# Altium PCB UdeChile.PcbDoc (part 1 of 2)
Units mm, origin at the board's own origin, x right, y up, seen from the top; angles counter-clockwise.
Board outline 201.93 x 30.26 mm, 2 copper layers (Top Layer, Bottom Layer); 212 components, 140 nets, 743 pads, 138 vias.
Unrouted connection lines stored in the file: 2.
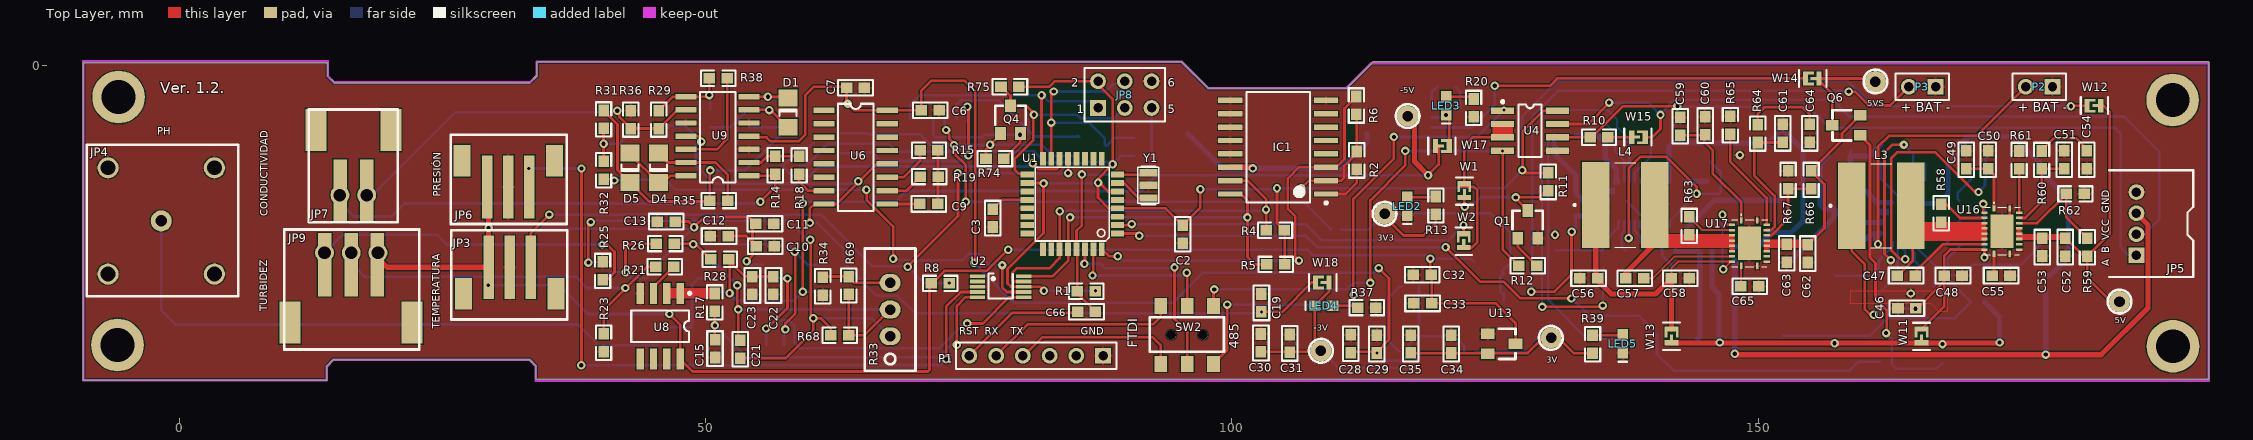
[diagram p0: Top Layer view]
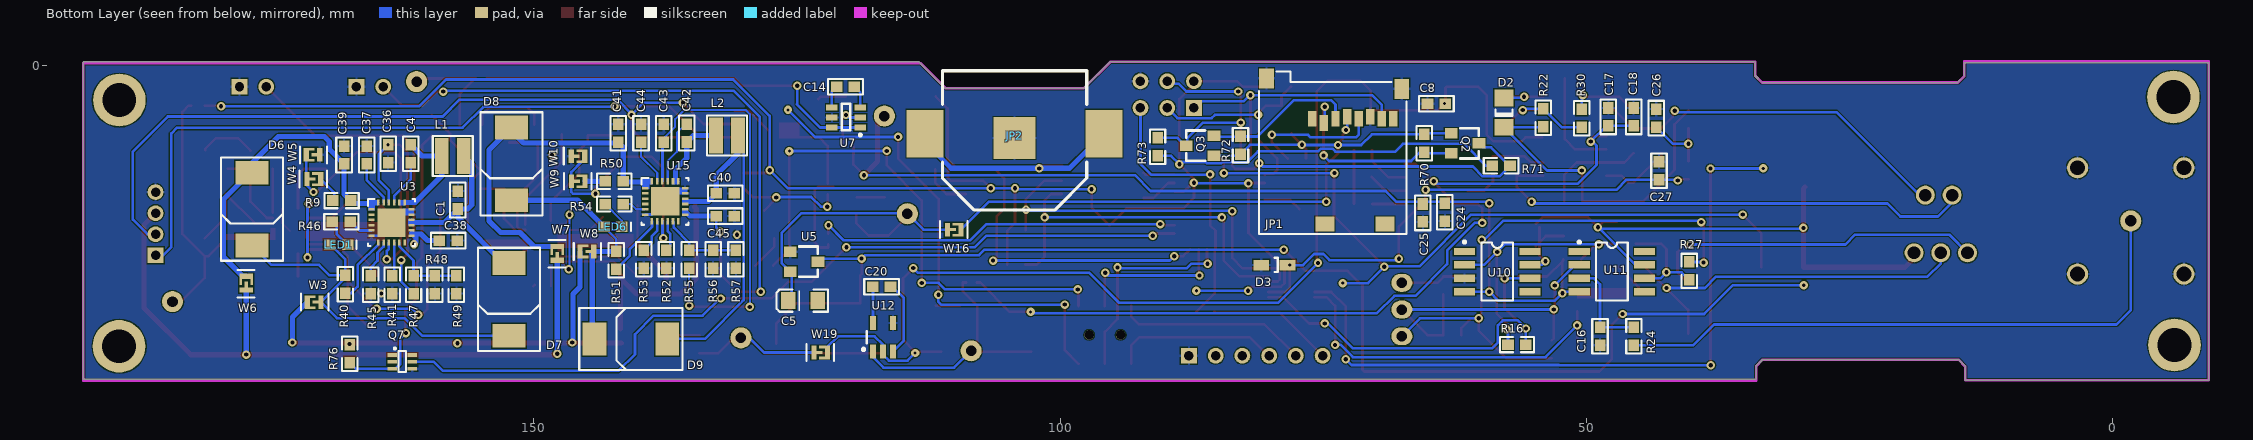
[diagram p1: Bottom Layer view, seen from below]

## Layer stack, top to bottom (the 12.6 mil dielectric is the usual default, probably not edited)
Top Layer: signal copper 0.0356
Dielectric: dielectric 0.32, FR-4, Dk 4.8
Bottom Layer: signal copper 0.0356

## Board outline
-9.13,-29.914 14.011,-29.914 14.011,-28.592 14.651,-27.952 33.247,-27.952 33.875,-28.58 33.875,-29.829 192.799,-29.829 192.799,0.339 192.796,0.336 113.375,0.336 110.88,-2.159 97.734,-2.159 95.23,0.345 95.224,0.339 33.949,0.339 33.949,-0.983 33.31,-1.622 14.713,-1.622 14.086,-0.995 14.086,0.264 -9.12,0.264 -9.13,0.254

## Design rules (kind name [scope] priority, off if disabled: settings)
Clearance [All] p1: gap=0.1
PolygonConnect [All] p1: connectstyle=Relief reliefconductorwidth=0.254 reliefentries=4 polygonreliefangle="90 Angle"
RoutingVias [All] p1: holewidth=0.711 width=1.27 viastyle="Through Hole" minholewidth=0.711 minwidth=1.27 maxholewidth=0.711 maxwidth=1.27
SilkscreenOverComponentPads SilkToSolderMaskClearance [IsPad] p1: minsilkscreentomaskgap=0.254
SolderMaskExpansion [All] p1: expansion=0.102
Width [All] p1: maxlimit=0.5 minlimit=0.2 preferedwidth=0.25
27 further rules are at their usual default settings.

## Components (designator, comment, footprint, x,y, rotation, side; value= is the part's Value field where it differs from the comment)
C1 "0.1uF" "Cap 0.1uF 0603 SMD" 157.202,-12.786 r270 bottom
C2 "0.1uF" "Cap 0.1uF 0603 SMD" 95.312,-16.034 r90 top
C3 "0.1uF" "Cap 0.1uF 0603 SMD" 77.261,-14.501 r90 top
C4 "47nF" "Cap 0.1uF 0603 SMD" 161.671,-8.382 r90 bottom
C5 "100uF" "Cap tant 10uF 1206 SMD" 123.011,-22.344 r0 bottom
C6 "0.1uF" "Cap 0.1uF 0603 SMD" 71.332,-4.262 r0 top
C7 "4.7uF" "Cap 0.1uF 0603 SMD" 64.236,-2.131 r180 top
C8 "0.1uF" "Cap 0.1uF 0603 SMD" 64.242,-3.64 r180 bottom
C9 "1nF" "Cap 0.1uF 0603 SMD" 71.2,-13.159 r0 top
C10 "0.1uF" "Cap 0.1uF 0603 SMD" 55.665,-17.172 r180 top
C11 "10uF" "Cap 0.1uF 0603 SMD" 55.628,-15.047 r180 top
C12 "0.1uF" "Cap 0.1uF 0603 SMD" 51.28,-16.206 r0 top
C13 "10uF" "Cap 0.1uF 0603 SMD" 46.249,-14.831 r0 top
C14 "0.1uF" "Cap 0.1uF 0603 SMD" 120.383,-2.013 r180 bottom
C15 "0.1uF" "Cap 0.1uF 0603 SMD" 50.892,-26.9 r270 top
C16 "2.2nF" "Cap 0.1uF 0603 SMD" 48.701,-25.735 r270 bottom
C17 "4.7uF" "Cap 0.1uF 0603 SMD" 47.906,-4.891 r90 bottom
C18 "0.1uF" "Cap 0.1uF 0603 SMD" 45.515,-4.891 r90 bottom
C19 "0.1uF" "Cap 0.1uF 0603 SMD" 102.802,-22.565 r90 top
C20 "0.1uF" "Cap 0.1uF 0603 SMD" 116.954,-21.04 r0 bottom
C21 "1uF" "Cap 0.1uF 0603 SMD" 53.295,-26.97 r90 top
C22 "0.1uF" "Cap 0.1uF 0603 SMD" 56.442,-20.907 r270 top
C23 "10uF" "Cap 0.1uF 0603 SMD" 54.446,-20.907 r270 top
C24 "0.1uF" "Cap 0.1uF 0603 SMD" 63.442,-13.943 r270 bottom
C25 "10uF" "Cap 0.1uF 0603 SMD" 65.529,-14.013 r270 bottom
C26 "1uF" "Cap 0.1uF 0603 SMD" 43.366,-5.004 r90 bottom
C27 "1uF" "Cap 0.1uF 0603 SMD" 43.098,-9.996 r90 bottom
C28 "0.1uF" "Cap 0.1uF 0603 SMD" 111.283,-26.443 r270 top
C29 "0.1uF" "Cap 0.1uF 0603 SMD" 113.765,-26.466 r270 top
C30 "0.1uF" "Cap 0.1uF 0603 SMD" 102.755,-26.367 r270 top
C31 "0.1uF" "Cap 0.1uF 0603 SMD" 105.49,-26.411 r270 top
C32 "0.1uF" "Cap 0.1uF 0603 SMD" 118.073,-19.885 r0 top
C33 "0.1uF" "Cap 0.1uF 0603 SMD" 118.114,-22.609 r0 top
C34 "0.1uF" "Cap 0.1uF 0603 SMD" 120.838,-26.466 r270 top
C35 "0.1uF" "Cap 0.1uF 0603 SMD" 116.973,-26.465 r270 top
C36 "4.7uF" "Cap 0.1uF 0603 SMD" 163.83,-8.382 r270 bottom
C37 "10uF" "Cap 0.1uF 0603 SMD" 165.862,-8.509 r270 bottom
C38 "10uF" "Cap 0.1uF 0603 SMD" 158.115,-16.637 r0 bottom
C39 "10uF" "Cap 0.1uF 0603 SMD" 168.021,-8.509 r270 bottom
C40 "0.1uF" "Cap 0.1uF 0603 SMD" 131.805,-12.152 r0 bottom
C41 "10uF" "Cap 0.1uF 0603 SMD" 141.965,-6.437 r270 bottom
C42 "47nF" "Cap 0.1uF 0603 SMD" 135.453,-6.42 r270 bottom
C43 "4.7uF" "Cap 0.1uF 0603 SMD" 137.647,-6.437 r90 bottom
C44 "10uF" "Cap 0.1uF 0603 SMD" 139.806,-6.437 r270 bottom
C45 "10uF" "Cap 0.1uF 0603 SMD" 131.805,-14.311 r0 bottom
C46 "0.1uF" "Cap 0.1uF 0603 SMD" 164.122,-23.063 r180 top
C47 "0.1uF" "Cap 0.1uF 0603 SMD" 164.047,-19.96 r0 top
C48 "47uF" "Cap 0.1uF 0603 SMD" 168.503,-19.963 r180 top
C49 "1uF" "Cap 0.1uF 0603 SMD" 169.747,-8.96 r90 top
C50 "1uF" "Cap 0.1uF 0603 SMD" 171.841,-8.96 r90 top
C51 "51pF" "Cap 0.1uF 0603 SMD" 179.064,-8.96 r90 top
C52 "47uF" "Cap 0.1uF 0603 SMD" 179.178,-17.262 r270 top
C53 "47uF" "Cap 0.1uF 0603 SMD" 176.98,-17.255 r270 top
C54 "1nF" "Cap 0.1uF 0603 SMD" 181.219,-8.958 r270 top
C55 "82nF" "Cap 0.1uF 0603 SMD" 173.066,-19.96 r0 top
C56 "0.1uF" "Cap 0.1uF 0603 SMD" 133.884,-20.221 r180 top
C57 "0.1uF" "Cap 0.1uF 0603 SMD" 138.259,-20.218 r0 top
C58 "47uF" "Cap 0.1uF 0603 SMD" 142.599,-20.221 r180 top
C59 "1uF" "Cap 0.1uF 0603 SMD" 142.586,-5.788 r90 top
C60 "1uF" "Cap 0.1uF 0603 SMD" 144.948,-5.719 r90 top
C61 "51pF" "Cap 0.1uF 0603 SMD" 152.334,-6.457 r90 top
C62 "47uF" "Cap 0.1uF 0603 SMD" 154.718,-17.875 r270 top
C63 "47uF" "Cap 0.1uF 0603 SMD" 152.698,-17.85 r270 top
C64 "1nF" "Cap 0.1uF 0603 SMD" 154.903,-6.456 r270 top
C65 "82nF" "Cap 0.1uF 0603 SMD" 149.198,-20.988 r0 top
C66 "0.1uF" "Cap 0.1uF 0603 SMD" 86.181,-23.388 r180 top
D1 "1N4148" "Diodo 1N4148 SMD" 57.824,-5.879 r90 top
D2 "1N4148" "Diodo 1N4148 SMD" 57.824,-3.079 r270 bottom
D3 "SDM100K30L-7" "Diodo SDM100K30L-7 SMD" 80.886,-18.974 r180 bottom
D4 "1N4148" "Diodo 1N4148 SMD" 45.512,-8.331 r270 top
D5 "1N4148" "Diodo 1N4148 SMD" 42.824,-8.331 r270 top
D6 "SM15T36CA" SM15T36CA 177.165,-12.827 r270 bottom
D7 "SM15T36CA" SM15T36CA 152.751,-21.395 r270 bottom
D8 "SM15T36CA" SM15T36CA 152.507,-8.522 r270 bottom
D9 "SM15T36CA" SM15T36CA 139.957,-25.588 r0 bottom
IC1 "DS3231" "RTC DS323116-SOIC" 108.946,-12.21 r180 top
JP1 "Socket uSD" "uSD Socket" 81.089,-15.896 r270 bottom
JP2 "Socket SMD" "Socket Pila 12mm SMD" 104.323,-6.885 r180 bottom
JP3 "3 pines" "JST SMD 3 PINES" 31.381,-19.177 r0 top
JP4 "BNC Conector" "BNC Conector" -1.718,-14.772 r90 top
JP5 "Grove" "JST TH 4 Pines - Horizontal" 185.928,-18.034 r0 top
JP6 "3 pines" "JST SMD 3 PINES" 31.254,-11.557 r180 top
JP7 "JST SMD" "JST SMD 2 pines - 2.54mm" 17.795,-11.938 r180 top
JP8 "ISP" HDR2X3 87.28,-4.039 r0 top
JP9 "3 pines" "JST SMD 3 PINES - 2.54mm" 16.317,-18.94 r0 top
L1 "1uH" 74438336010 157.607,-8.636 r180 bottom
L2 "1uH" 74438336010 131.551,-6.691 r180 bottom
L3 "1uH" SRN8040-1R0Y 162.28,-13.569 r0 top
L4 "1uH" SRN8040-1R0Y 137.957,-13.494 r0 top
LED1 "LED Rojo" "LED Rojo 0603" 168.529,-17.018 r180 bottom
LED2 "LED Rojo" "LED Rojo 0603" 116.674,-13.364 r270 top
LED3 "LED Rojo" "LED Rojo 0603" 120.365,-3.815 r270 top
LED4 "LED Rojo" "LED Rojo 0603" 108.702,-22.838 r180 top
LED5 "LED Rojo" "LED Rojo 0603" 137.142,-26.448 r270 top
LED6 "LED Rojo" "LED Rojo 0603" 142.473,-15.327 r180 bottom
P1 "Header 6" HDR1X6 87.758,-27.577 r180 top
P2 "Header 2" HDR1X2 177.953,-2.022 r180 top
P3 "Header 2" HDR1X2 166.849,-2.022 r180 top
Q1 "BSS123" "MOSFET BSS123  SMD SOT-23" 128.1,-15.105 r0 top
Q2 "BSS123" "MOSFET BSS123  SMD SOT-23" 61.524,-7.399 r270 bottom
Q3 "BSS123" "MOSFET BSS123  SMD SOT-23" 86.694,-7.613 r90 bottom
Q4 "BSS123" "MOSFET BSS123  SMD SOT-23" 78.962,-5.147 r0 top
Q6 "FDN340P" "MOSFET FDN340P SSOT3" 158.356,-5.75 r90 top
Q7 "DDC123JU" "Transistor array DDC123JU-FDICT SMD" 163.445,-27.509 r270 bottom
R1 "10K" "Res 1K 0603 1/8W" 86.156,-21.448 r0 top
R2 "10K" "Res 10K 0603 1/10W" 111.853,-9.027 r270 top
R4 "22K" "Res 1K 0603 1/8W" 104.102,-15.652 r0 top
R5 "22K" "Res 1K 0603 1/8W" 104.153,-18.906 r0 top
R6 "10K" "Res 10K 0603 1/10W" 111.825,-3.804 r90 top
R8 "4k7" "Res 10K 0603 1/10W" 72.284,-20.71 r0 top
R9 "10K" "Res 1K 0603 1/8W" 168.252,-12.831 r0 bottom
R10 "120R" "Res 1K 0603 1/8W" 134.871,-6.812 r180 top
R11 "10K" "Res 10K 0603 1/10W" 130.054,-11.064 r90 top
R12 "Res 10K SMD" "Res 10K 0603 1/10W" 128.1,-19.022 r180 top
R13 "1K" "Res 1K 0603 1/8W" 119.378,-13.305 r270 top
R14 "6K8" "Res 1K 0603 1/8W" 56.608,-9.478 r90 top
R15 "100K" "Res 1K 0603 1/8W" 71.219,-8.058 r0 top
R16 "30K" "Res 1K 0603 1/8W" 56.591,-26.524 r180 bottom
R17 "1K" "Res 1K 0603 1/8W" 50.877,-22.513 r90 top
R18 "100K" "Res 1K 0603 1/8W" 58.873,-9.492 r270 top
R19 "10K" "Res 1K 0603 1/8W" 71.238,-10.562 r0 top
R20 "1K" "Res 1K 0603 1/8W" 122.962,-4.04 r90 top
R21 "10K" "Res 1K 0603 1/8W" 46.109,-19.131 r180 top
R22 "10k" "Res 1K 0603 1/8W" 54.09,-4.972 r90 bottom
R23 "4K7" "Res 1K 0603 1/8W" 40.301,-26.338 r90 top
R24 "4M7" "Res 1K 0603 1/8W" 45.483,-25.735 r270 bottom
R25 "500R" "Res 1K 0603 1/8W" 40.205,-19.515 r270 top
R26 "30K" "Res 1K 0603 1/8W" 46.152,-16.926 r0 top
R27 "2K2" "Res 1K 0603 1/8W" 40.228,-19.52 r90 bottom
R28 "75K" "Res 1K 0603 1/8W" 51.333,-18.409 r180 top
R29 "5K6" "Res 1K 0603 1/8W" 45.547,-5.146 r270 top
R30 "10k" "Res 1K 0603 1/8W" 50.432,-5.021 r90 bottom
R31 "10k" "Res 1K 0603 1/8W" 40.301,-5.13 r90 top
R32 "10k" "Res 1K 0603 1/8W" 40.301,-9.961 r90 top
R33 "TRIM 5K" "TRIMPOT TH" 67.528,-23.193 r180 top
R34 "1K" "Res 1K 0603 1/8W" 61.135,-20.985 r90 top
R35 "10k" "Res 1K 0603 1/8W" 51.245,-12.841 r0 top
R36 "1M" "Res 1K 0603 1/8W" 42.891,-5.146 r90 top
R37 "1K" "Res 1K 0603 1/8W" 112.804,-22.999 r180 top
R38 "10k" "Res 1K 0603 1/8W" 51.202,-1.22 r180 top
R39 "1K" "Res 1K 0603 1/8W" 134.252,-26.49 r270 top
R40 "2k2" "Res 1K 0603 1/8W" 167.894,-20.789 r270 bottom
R41 "1K" "Res 1K 0603 1/8W" 163.449,-20.828 r270 bottom
R45 "1K" "Res 1K 0603 1/8W" 165.481,-20.828 r270 bottom
R46 "2K2" "Res 1K 0603 1/8W" 168.275,-14.859 r180 bottom
R47 "5K23" "Res 1K 0603 1/8W" 161.417,-20.828 r270 bottom
R48 "30K" "Res 1K 0603 1/8W" 159.385,-20.828 r90 bottom
R49 "10K" "Res 1K 0603 1/8W" 157.353,-20.828 r90 bottom
R50 "10K" "Res 1K 0603 1/8W" 142.346,-11.009 r0 bottom
R51 "2k2" "Res 1K 0603 1/8W" 142.159,-18.503 r270 bottom
R52 "1K" "Res 1K 0603 1/8W" 137.393,-18.417 r270 bottom
R53 "1K" "Res 1K 0603 1/8W" 139.552,-18.417 r270 bottom
R54 "2K2" "Res 1K 0603 1/8W" 142.346,-13.168 r180 bottom
R55 "5K23" "Res 1K 0603 1/8W" 135.234,-18.417 r270 bottom
R56 "30K" "Res 1K 0603 1/8W" 132.955,-18.419 r90 bottom
R57 "10K" "Res 1K 0603 1/8W" 130.789,-18.419 r90 bottom
R58 "332K" "Res 1K 0603 1/8W" 167.376,-14.05 r270 top
R59 "324K" "Res 1K 0603 1/8W" 181.272,-17.272 r270 top
R60 "17K4" "Res 1K 0603 1/8W" 176.911,-8.976 r270 top
R61 "270K" "Res 1K 0603 1/8W" 174.772,-8.976 r270 top
R62 "100k" "Res 1K 0603 1/8W" 180.126,-12.208 r180 top
R63 "332K" "Res 1K 0603 1/8W" 143.442,-15.245 r270 top
R64 "17K4" "Res 1K 0603 1/8W" 149.941,-6.473 r270 top
R65 "270K" "Res 1K 0603 1/8W" 147.356,-5.672 r270 top
R66 "324K" "Res 1K 0603 1/8W" 155.022,-10.873 r90 top
R67 "100k" "Res 1K 0603 1/8W" 152.83,-10.873 r270 top
R68 "0" "Res 1K 0603 1/8W" 62.732,-25.629 r0 top
R69 "0" "Res 1K 0603 1/8W" 63.591,-20.907 r90 top
R70 "10K" "Res 10K 0603 1/10W" 65.402,-7.389 r90 bottom
R71 "10K" "Res 10K 0603 1/10W" 58.104,-9.534 r0 bottom
R72 "10K" "Res 10K 0603 1/10W" 82.856,-7.597 r270 bottom
R73 "10K" "Res 10K 0603 1/10W" 90.733,-7.734 r270 bottom
R74 "10K" "Res 10K 0603 1/10W" 77.482,-8.847 r180 top
R75 "10K" "Res 10K 0603 1/10W" 78.909,-2.028 r0 top
R76 "1K" "Res 1K 0603 1/8W" 167.485,-27.398 r90 bottom
SW2 "DPDT SMD" "SW INTERR SMD" 94.243,-25.605 r90 top
U1 "ATMEGA328" "ATMega328 32-TQFP SMD" 89.126,-15.971 r180 top
U2 "ADS1015IDGSR" ADS1015IDGSR 78.026,-21.007 r0 top
U3 "BQ25606RGER" BQ25606RGER 163.322,-14.986 r180 bottom
U4 "SN75176AD" "Transceiver SN75176AD SOCI8" 125.712,-4.297 r0 top
U5 "AP2120N-3.3TRG1" "Reg 3.3V 150mA SOT-23" 124.31,-18.649 r270 bottom
U6 "CD4060BM96" "C BINARY COUNTER/DIV/OSC CD4060BM 16SOIC" 64.252,-8.728 r0 top
U7 "LTC1983ES6-5" "Reg CHARGE PUMP -5V SOT-23-6" 118.979,-5.893 r90 bottom
U8 "LM358" "Op Amp LM358 8-SOIC SMD" 45.686,-24.765 r270 top
U9 "LMV324" "Op. Amp LM324 SO-14" 54.118,-10.467 r180 top
U10 "TL081BCD" "Amp. Op. CA3140AMZ SOIC8" 58.467,-19.587 r180 bottom
U11 "CA3140AMZ" "Amp. Op. CA3140AMZ SOIC8" 47.565,-19.587 r180 bottom
U12 "TPS60400DBVR" "Charge Pump Switching Regulator - TPS60400DBVR" 117.776,-27.17 r90 bottom
U13 "AP7361-33D" "Reg 3V 300mA SOT23-3" 125.625,-26.448 r270 top
U15 "BQ25606RGER" BQ25606RGER 137.328,-12.974 r180 bottom
U16 "TPS61088RHLR" TPS61088RHLR 173.255,-15.668 r0 top
U17 "TPS61088RHLR" TPS61088RHLR 149.258,-16.818 r0 top
W1 "Jumper" Jumper 122.082,-11.936 r90 top
W2 "Jumper" Jumper 122.022,-16.699 r90 top
W3 "Jumper" Jumper 170.815,-22.489 r0 bottom
W4 "Jumper" Jumper 170.942,-10.795 r180 bottom
W5 "Jumper" Jumper 170.923,-8.492 r0 bottom
W6 "Jumper" Jumper 177.318,-20.738 r90 bottom
W7 "Jumper" Jumper 147.769,-17.901 r90 bottom
W8 "Jumper" Jumper 144.898,-17.669 r0 bottom
W9 "Jumper" Jumper 145.82,-11.005 r180 bottom
W10 "Jumper" Jumper 145.846,-8.625 r180 bottom
W11 "Jumper" Jumper 165.513,-25.744 r90 top
W12 "Jumper" Jumper 181.938,-3.82 r180 top
W13 "Jumper" Jumper 141.764,-25.739 r90 top
W14 "Jumper" Jumper 155.181,-1.244 r180 top
W15 "Jumper" Jumper 138.574,-6.812 r0 top
W16 "Jumper" Jumper 110.099,-15.603 r180 bottom
W17 "Jumper" Jumper 119.946,-7.658 r0 top
W18 "Jumper" Jumper 108.628,-20.619 r180 top
W19 "Jumper" Jumper 122.785,-27.275 r180 bottom
Y1 "16MHz" "Xtal 16MHz SMD" 92.067,-11.388 r270 top

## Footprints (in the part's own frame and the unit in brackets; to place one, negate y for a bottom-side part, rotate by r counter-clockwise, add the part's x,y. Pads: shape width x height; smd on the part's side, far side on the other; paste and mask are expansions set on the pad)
74438336010 [mm] "FIXED IND 1UH 4A 32 MOHM SMD"
  rect 1.3x3.4 smd: 1(-1.141,0.035) 2(0.959,0.035)
  silkscreen extent -1.99,-1.87 1.81,1.94, body extent -1.59,-1.46 1.41,1.54, height 2
ADS1015IDGSR [mm] "ADS1015IDGSR"
  rect 1.45x0.35 smd: 1(-2.2,0.975) 2(-2.2,0.475) 3(-2.2,-0.015) 4(-2.2,-0.515) 5(-2.2,-1.015) 6(2.2,-1.015) 7(2.2,-0.515) 8(2.2,-0.015) 9(2.2,0.475) 10(2.2,0.975)
  silkscreen extent -1.15,-1.15 1.15,1.25
"Amp. Op. CA3140AMZ SOIC8" [mm] "CA3140AMZ-ND"
  rect 2x0.7 smd: 1(-3.11,1.905) 2(-3.11,0.635) 3(-3.11,-0.635) 4(-3.11,-1.905) 5(3.11,-1.905) 6(3.11,-0.635) 7(3.11,0.635) 8(3.11,1.905)
  silkscreen extent -3.23,-2.75 1.5,2.93
"ATMega328 32-TQFP SMD" [mil] "ATMEGA328P-AU-ND, 556-ATMEGA328P-AU, ATMEGA328P-AU"
  rect 50x22 smd: 1(0,0) 2(0.01,-31.5) 3(0.01,-63) 4(0.01,-94.49) 5(0.01,-125.99) 6(0.01,-157.48) 7(0,-188.98) 8(0,-220.48) 17(338.01,-220.47) 18(338.01,-188.98) 19(338.01,-157.48) 20(338,-125.99) 21(338,-94.49) 22(338,-62.99) 23(338,-31.5) 24(338,-0.01)
  rect 22x50 smd: 9(58.77,-279.24) 10(90.26,-279.24) 11(121.76,-279.23) 12(153.26,-279.24) 13(184.75,-279.24) 14(216.25,-279.24) 15(247.74,-279.24) 16(279.24,-279.24) 25(279.24,58.76) 26(247.74,58.76) 27(216.25,58.76) 28(184.75,58.76) 29(153.26,58.76) 30(121.76,58.76) 31(90.27,58.76) 32(58.77,58.77)
  silkscreen extent 31,-248 307,28
"BNC Conector" [mm] "51K204-400A5"
  round 2 hole 1.1: 1(0,0)
  round 2 hole 1.4: 2(-5.05,-5.05) 2(-5.05,5.05) 2(5.05,-5.05) 2(5.05,5.05)
  silkscreen extent -7.15,-7.3 7.22,7.07, body extent -7.15,-7.3 7.22,26.92, height 14.5
BQ25606RGER [mm] "IC BATT CHG LI-ION 1CELL 24VQFN"
  rect 0.6x0.24 smd mask+0.07: 1(-2.092,1.31) 2(-2.092,0.81) 3(-2.092,0.31) 4(-2.092,-0.19) 5(-2.092,-0.69) 6(-2.092,-1.19) 13(1.708,-1.19) 14(1.708,-0.69) 15(1.708,-0.19) 16(1.708,0.31) 17(1.708,0.81) 18(1.708,1.31)
  rect 0.24x0.6 smd mask+0.07: 7(-1.442,-1.84) 8(-0.942,-1.84) 9(-0.442,-1.84) 10(0.058,-1.84) 11(0.558,-1.84) 12(1.058,-1.84) 19(1.058,1.96) 20(0.558,1.96) 21(0.058,1.96) 22(-0.442,1.96) 23(-0.942,1.96) 24(-1.442,1.96)
  rect 2.7x2.7 smd paste-1.337 mask+0.07: 25(-0.192,0.06)
  silkscreen extent -2.42,-2.16 2.03,2.29
"C BINARY COUNTER/DIV/OSC CD4060BM 16SOIC" [mm] "296-31513-2-ND"
  rect 2x0.51 smd: 1(-3,4.457) 2(-3,3.187) 3(-3,1.917) 4(-3,0.647) 5(-3,-0.623) 6(-3,-1.893) 7(-3,-3.163) 8(-3,-4.433) 9(3,-4.433) 10(3,-3.163) 11(3,-1.893) 12(3,-0.623) 13(3,0.647) 14(3,1.917) 15(3,3.187) 16(3,4.457)
  silkscreen extent -1.68,-5.09 1.7,5.09
"Cap 0.1uF 0603 SMD" [mm] "490-1532-2-ND, 81-GRM39X104K16, GRM188R71C104KA01D"
  rect 1.1x1 smd: 1(-0.85,0) 2(0.85,0)
  silkscreen extent -1.65,-0.74 1.65,0.74
"Cap tant 10uF 1206 SMD" [mm] "478-1655-1-ND, 581-TAJA106K016R, TAJA106K016RNJ"
  rect 1.4x1.6 smd: 1(2.8,0) 2(0,0)
  silkscreen extent -0.95,-1.06 3.91,1.05
"Charge Pump Switching Regulator - TPS60400DBVR" [mm] "2156-TPS60400DBVR-ND"
  rect 1.3x0.6 smd: 1(0,0) 2(0,-0.95) 3(0,-1.9) 4(2.7,-1.9) 5(2.7,0)
  silkscreen extent 0.08,0.6 1.92,1.01
"Diodo 1N4148 SMD" [mm] "568-1749-1-ND, 771-PMLL4148L-T/R, PMLL4148L 115"
  rect 1.6x1.8 smd: 1(0,0) 2(2.8,0)
  silkscreen extent 1.1,-0.8 1.7,0.8
"Diodo SDM100K30L-7 SMD" [mm] "SDM100K30LDITR-ND"
  rect 1.5x1 smd: 1(0,0) 2(2.5,0)
  silkscreen extent 1.25,-0.65 1.6,0.7
HDR1X2 [mm] "Connector; Header; 2 Position"
  rect 1.5x1.5 hole 0.9: 1(0,0)
  round 1.5 hole 0.9: 2(2.54,0)
  silkscreen extent -1.27,-1.27 3.81,1.27
HDR1X6 [mm] "Connector; Header; 6 Position"
  rect 1.5x1.5 hole 0.9: 1(0,0)
  round 1.5 hole 0.9: 2(2.54,0) 3(5.08,0) 4(7.62,0) 5(10.16,0) 6(12.7,0)
  silkscreen extent -1.27,-1.27 13.97,1.27
HDR2X3 [mm] "Connector; Header; 3x2 Position"
  rect 1.5x1.5 hole 0.9: 1(0,0)
  round 1.5 hole 0.9: 2(0,2.54) 3(2.54,0) 4(2.54,2.54) 5(5.08,0) 6(5.08,2.54)
  silkscreen extent -1.27,-1.27 6.35,3.81
"JST SMD 2 pines - 2.54mm" [mm]
  rect 1.3x6 smd: 1(2.5,0) 2(0,0)
  rect 2x4 smd: 3(4.8,-5.8) 4(-2.3,-5.8)
  silkscreen extent -2.95,-7.75 5.5,2.98, body extent -2.95,-7.75 5.45,3.03, height 7.9
"JST SMD 3 PINES" [mm] "455-1735-1-ND, , B3B-PH-SM4-TB(LF)(SN)(P)"
  rect 1x6 smd: 1(2,0) 2(0,0) 3(-2,0)
  rect 1.6x3 smd: 4(4.4,-2.5) 5(-4.4,-2.5)
  silkscreen extent -5.56,-4.96 5.46,3.51, body extent -5.43,-4.87 5.3,3.4, height 7.9
"JST SMD 3 PINES - 2.54mm" [mm] "455-1735-1-ND, , B3B-PH-SM4-TB(LF)(SN)(P)"
  rect 1.3x6 smd: 1(2.5,0) 2(0,0) 3(-2.5,0)
  rect 2x4 smd: 4(5.8,-5.5) 5(-5.8,-5.5)
  silkscreen extent -6.35,-8.05 6.48,3.35, body extent -6.35,-7.4 6.53,3.4, height 7.9
"JST TH 4 Pines - Horizontal" [mm] "Seeed: 110990030"
  rect 1.5x1.5 hole 0.9: 1(0,0)
  round 1.5 hole 0.9: 2(0,2) 3(0,4) 4(0,6)
  silkscreen extent -2.6,-2.08 5.41,8.08, body extent -2.7,-2.18 5.51,8.18, height 7.9
Jumper [mm]
  rect 0.5x1.3 smd: 1(-0.6,0) 2(0.7,0)
  rect 1x0.3 smd: 1(-0.3,0)
  rect 1x0.25 smd: 2(0.4,0.525) 2(0.4,-0.525)
  silkscreen extent -1.3,-0.8 1.3,0.8
"LED Rojo 0603" [mm] "475-2512-1-ND, 720-LSQ976-NR-1, LS Q976-NR-1"
  rect 1.1x1 smd: 1(-0.85,0) 2(0.85,0)
  silkscreen extent 1.7,-0.4 1.7,0.4
"MOSFET BSS123  SMD SOT-23" [mm] "BSS123NCT-ND, 512-BSS123, BSS123"
  rect 1x1.2 smd: 1(-0.95,-1.32) 2(0.95,-1.32) 3(0,1.32)
  silkscreen extent -1.44,-0.47 1.44,1.31
"MOSFET FDN340P SSOT3" [mm] "FDN340PCT-ND,,FDN340P"
  rect 1x1.2 smd: 1(-0.9,-1.32) 2(1,-1.32) 3(0.05,1.32)
  silkscreen extent -1.39,-0.47 1.49,1.31
"Op Amp LM358 8-SOIC SMD" [mm] "LM358DGOS-ND, 863-LM358DG, LM358DG"
  rect 2x0.7 smd: 1(-3.11,1.905) 2(-3.11,0.635) 3(-3.11,-0.635) 4(-3.11,-1.905) 5(3.11,-1.905) 6(3.11,-0.635) 7(3.11,0.635) 8(3.11,1.905)
  silkscreen extent -3.23,-2.75 1.5,2.93
"Op. Amp LM324 SO-14" [mm] "LMV324BG-13DITR-ND"
  rect 2x0.51 smd: 1(0,0) 2(0,-1.25) 3(0,-2.5) 4(0,-3.75) 5(0,-5) 6(0,-6.25) 7(0,-7.5) 8(6,-7.5) 9(6,-6.25) 10(6,-5) 11(6,-3.75) 12(6,-2.5) 13(6,-1.25) 14(6,0)
  silkscreen extent 1.27,-7.95 4.65,0.64
"Reg 3.3V 150mA SOT-23" [mm] "AP2120N-3.3TRG1DICT-ND,,AP2120N-3.3TRG1"
  rect 1x1.2 smd: 1(-0.95,-1.32) 2(0.95,-1.32) 3(0,1.32)
  silkscreen extent -1.44,-0.47 1.44,1.31
"Reg 3V 300mA SOT23-3" [mm] "AP2125N-3.0TRG1DITR-ND"
  rect 1x1.3 smd: 1(-0.95,-1.32) 2(0.95,-1.32) 3(0,1.32)
  silkscreen extent -1.44,-0.25 1.44,1.31
"Reg CHARGE PUMP -5V SOT-23-6" [mm] "LTC1983ES6-5#TRPBFTR-ND"
  rect 0.6x1.1 smd: 1(0,0) 2(0.95,0) 3(1.9,0) 4(1.9,2.7) 5(0.95,2.7) 6(0,2.7)
  silkscreen extent -0.82,-0.11 2.25,1.75
"Res 1K 0603 1/8W" [mm] "RNCP0603FTD1K00CT-ND, 660-SG73S1JTTD1001F, RNCP0603FTD1K00"
  rect 1.1x1 smd: 1(-0.85,0) 2(0.85,0)
  silkscreen extent -1.63,-0.73 1.63,0.73
"Res 10K 0603 1/10W" [mm] "P10KGCT-ND, 667-ERJ-3GEYJ103V, ERJ-3GEYJ103V"
  rect 1.1x1 smd: 1(-0.85,0) 2(0.85,0)
  silkscreen extent -1.65,-0.73 1.64,0.73
"RTC DS323116-SOIC" [mm] "DS3231SN#T&RTR-ND"
  rect 2.3x0.51 smd: 1(0,0) 2(0,-1.27) 3(0,-2.54) 4(0,-3.81) 5(0,-5.08) 6(0,-6.35) 7(0,-7.62) 8(0,-8.89) 9(9.1,-8.89) 10(9.1,-7.62) 11(9.1,-6.35) 12(9.1,-5.08) 13(9.1,-3.81) 14(9.1,-2.54) 15(9.1,-1.27) 16(9.1,0)
  silkscreen extent -0.13,-9.69 7.55,0.97
SM15T36CA [mm] "TVS DIODE 30.8V 64.3V SMC"
  rect 2.25x3.15 smd: 1(4.274,0.391) 2(-2.626,0.391)
  silkscreen extent -4.08,-2.56 5.72,3.34, body extent -3.15,-2.56 4.8,3.34, height 2.65
"Socket Pila 12mm SMD" [mm] "BK-885-ND, , BK-885"
  rect 3.5x4.5 smd: 1(-8.5,0.4) 1(8.5,0.4)
  rect 3.96x3.96 smd: 2(0,0)
  silkscreen extent -6.86,-6.86 6.86,6.38, body extent -6.85,-6.86 6.9,6.38, height 3.18
SRN8040-1R0Y [mm] "FIXED IND 1UH 7.8A 10 MOHM SMD"
  rect 2.6x8.2 smd: 1(-3.403,0.238) 2(2.197,0.238)
  silkscreen extent -5.5,-3.76 0.4,4.24, body extent -4.6,-3.76 3.4,4.24, height 4
"SW INTERR SMD" [mm] ", , ,spkf: COM-00597"
  rect 1.5x1.2 smd: 1(-2.75,1) 2(-2.75,-1.5) 3(-2.75,-4) 4(2.75,-4) 5(2.75,-1.5) 6(2.75,1)
  round 0.87 hole 0.9 mask+0.102: 7(0,0) 8(0,-3)
  silkscreen extent -1.61,-5 1.69,2.06
TPS61088RHLR [mm] "IC REG BOOST ADJ 10A 20VQFN"
  rect 0.24x0.6 smd mask+0.06: 1(-0.86,2.079) 10(-0.86,-2.221) 11(0.64,-2.221) 20(0.64,2.079)
  rect 0.6x0.24 smd mask+0.06: 2(-1.76,1.679) 3(-1.76,1.179) 4(-1.76,0.679) 6(-1.76,-0.321) 7(-1.76,-0.821) 8(-1.76,-1.321) 12(1.54,-1.821) 13(1.54,-1.321) 14(1.54,-0.821) 15(1.54,-0.321) 16(1.54,0.179) 17(1.54,0.679) 18(1.54,1.179) 19(1.54,1.679)
  rect 0.6x0.24 smd paste+0 mask+0.06: 5(-1.76,0.179) 9(-1.76,-1.821)
  rect 2.19x3.19 smd mask+0.06: 21(-0.11,-0.071)
  silkscreen extent -1.76,-2.32 1.64,2.68, body extent -1.86,-2.32 1.64,2.18, height 1.1
"Transceiver SN75176AD SOCI8" [mm] "296-6857-5-ND, 595-SN75176AD, SN75176AD"
  rect 2.2x0.6 smd: 1(0,0) 2(0,-1.27) 3(0,-2.54) 4(0,-3.81) 5(5.2,-3.81) 6(5.2,-2.54) 7(5.2,-1.27) 8(5.2,0)
  silkscreen extent -0.12,-4.4 3.7,0.97
"Transistor array DDC123JU-FDICT SMD" [mm] "DDC123JU-FDICT-ND, 621-DDC123JU-F, DDC123JU-7-F"
  rect 0.35x0.9 smd: 1(0,0) 2(0.65,0) 3(1.3,0) 4(1.3,1.9) 5(0.65,1.9) 6(0,1.9)
  silkscreen extent -0.69,0.18 1.61,1.3
"TRIMPOT TH" [mm] "3296W-103LF-ND, , 3296W-1-103LF"
  oval 2x1.7 hole 1: 1(0,2.54) 2(0,0) 3(0,-2.54)
  silkscreen extent -2.41,-5.8 2.41,5.8
"uSD Socket" [mm] "MCI-PRT-00176"
  rect 1.9x1.4 smd: 0(-14.675,0.7) 0(-13.675,13.55)
  rect 1.5x0.8 smd: 1(-10.825,5.06) 2(-10.425,6.16) 3(-10.825,7.26) 4(-11.025,8.36) 5(-10.825,9.46) 6(-11.025,10.56) 7(-10.825,11.66) 8(-10.825,12.76)
  rect 1.4x1.8 smd: 9(-0.825,6.25) 10(-0.825,11.95)
  silkscreen extent -15.32,0 0.13,14
"Xtal 16MHz SMD" [mm] "490-1198-1-ND, 81-CSTCE16M0V53-R0, CSTCE16M0V53-R0"
  rect 0.7x1.7 smd: 1(-1.2,0) 2(0,0) 3(1.2,0)
  silkscreen extent -1.8,-1 1.8,1

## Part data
C1 C2 C3 C4 C6 C8 C9 C10 C11 C12 C13 C15 C17 C19 C21 C22 C23 C24 C25 C28 C30 C32 C34 C36 C37 C38 C39 C40 C41 C42 C43 C44 C45 C46 C47 C48 C49 C50 C51 C52 C53 C54 C55 C56 C57 C58 C59 C60 C61 C62 C63 C64 C65 C66: library part "Capacitor 0.1uF SMD", "0.1uF 16V"
C5: library part "Cap TANT 100uF", "CAP TANT 100UF 6.3V 20% 1206"
C7 C18 C26 C27: library part "Capacitor 0.1uF SMD"
C14 C20: library part "Capacitor 0.1uF SMD", "1uF 16V"
C16: library part "Capacitor 0.1uF SMD", "2.2nF 16V"
C29 C31 C33 C35: library part "Capacitor 0.1uF SMD", "10uF 16V"
D1 D2 D4 D5: library part "Diodo 4148", "Diodo 4148 SMD"
D3: library part "Diodo SDM100K30L-7", "Diodo SDM100K30L-7 SMD"
D6 D7 D8 D9: "TVS DIODE 30.8V 64.3V SMC"
IC1: "IC RTC CLK/CALENDAR I2C 16-SOIC"
JP2: library part "Socket Pila 12mm SMD"
JP3 JP6: library part "JST 3 pines", "485-4391"
JP5: library part "JST 4 pines_Horizontal", "713-110990037"
JP7: library part "JST 2 pines_2.54mm", "2 pines"
JP8: library part "Header 3X2", "Header, 3-Pin, Dual row"
JP9: library part "JST 3 pines 2.54mm"
L1 L2: library part 74438336010, "FIXED IND 1UH 4A 32 MOHM SMD"
L3 L4: library part SRN8040-1R0Y, "FIXED IND 1UH 7.8A 10 MOHM SMD"
LED1 LED2 LED3 LED4 LED5 LED6: "LED Rojo 0603"
P1: "Header, 6-Pin"
P2 P3: "Header, 2-Pin"
Q1 Q2 Q3 Q4: library part "MOSFET N-Channel_2", "MOSFET N-CH 100V 170MA"
Q6: library part "MOSFET P-Channel_3", "MOSFET P-CH 20V 2A SSOT3"
Q7: library part "Trans Array Dual NPN", "Transistor Array 100mA"
R1 R4 R5 R9 R10 R13 R14 R15 R16 R17 R18 R19 R20 R21 R22 R23 R24 R25 R26 R27 R28 R29 R30 R31 R32 R34 R35 R36 R37 R38 R39 R40 R41 R45 R46 R47 R48 R49 R50 R51 R52 R53 R54 R55 R56 R57 R58 R59 R60 R61 R62 R63 R64 R65 R66 R67 R68 R69 R76: library part "Res 1K SMD", "1K SMD"
R2 R6 R11 R70 R71 R72 R73 R74 R75: library part "Res 10K SMD"
R8: library part "Res 10K SMD", "10K"
R12: "10K"
R33: library part "TRIMMER 10K OHM", "TRIMMER 10K OHM 0.5W PC PIN"
SW2: library part "SW interruptor"
U1: "IC ATMega328"
U3 U15: "IC BATT CHG LI-ION 1 CELL 24VQFN"
U4: "Transceiver Differential Bus 5V"
U5: library part "Reg 3.3V 150mA AP2120N", "IC REG LINEAR 3.3V 150MA SOT23"
U6: library part "IC Binary Counter Element Bit Negative"
U7: "REG CHARGE PUMP -5V TSOT23-6"
U8: library part "Op Amp 358", "Op Amp LM358"
U9: "Op. Amp. GP 4 CIRCUIT 14SO"
U10: "Operational Amplifier"
U11: "Operational Amplifier with MOSFET"
U12: library part "TPS60400 60MA CHARGE PUMP VOLTAG", "Reg. inv. -3v"
U13: library part "REG LINEAR 3V 300MA SOT23-3", "Regulador 3 0.3mA AP2125N-3.0TRG1"
U16 U17: "IC REG BOOST ADJ 10A 20VQFN"
W1 W2 W3 W4 W5 W6 W7 W8 W9 W10 W11 W12 W13 W14 W15 W16 W17 W18 W19: "Jumper Wire"
Y1: library part "XTAL 16MHz"

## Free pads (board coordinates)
  round 5 hole 3.2: 0(-5.872,-26.556) 0(-5.773,-3.004) 0(189.364,-3.29) 0(189.395,-26.679)
  round 1.8 hole 1.2: 1(18.87,-17.804) 2(16.33,-17.804) 2(17.795,-12.319) 3(13.79,-17.804) 3(15.255,-12.319)
  round 2 hole 1: 1(108.451,-27.11) 1(114.501,-14.09) 1(116.69,-4.809) 1(130.316,-25.882) 1(161.131,-1.538) 1(184.319,-22.44)

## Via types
v1: diameter 0.8/0.8 (per signal layer), hole 0.4, Top Layer to Bottom Layer, tented both sides, 126 vias
v2: diameter 0.8/0.8 (per signal layer), hole 0.3, Top Layer to Bottom Layer, tented bottom, 6 vias
v3: diameter 0.8/0.8 (per signal layer), hole 0.3, Top Layer to Bottom Layer, tented top, 3 vias
v4: diameter 0.6/0.8 (per signal layer), hole 0.3, Top Layer to Bottom Layer, tented bottom, 2 vias
v5: diameter 0.8/0.8 (per signal layer), hole 0.4, Top Layer to Bottom Layer, tented bottom, 1 vias

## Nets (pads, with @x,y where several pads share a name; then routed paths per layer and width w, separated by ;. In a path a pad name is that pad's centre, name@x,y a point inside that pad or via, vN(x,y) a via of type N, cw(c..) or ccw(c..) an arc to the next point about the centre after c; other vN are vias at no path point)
3V: C6.1 C7.2 C8.2 C28.2 C29.2 U6.16 U9.4 U12.2 W19.2 | length 110.4
  Top Layer w0.25: U9.4@54.186,-6.836 55.779,-6.836 56.154,-7.21 58.842,-7.21 59.47,-6.582 59.47,-2.832 60.29,-2.011 63.266,-2.011 C7.2@63.386,-2.131 v3@63.386,-3.527 ; v3(63.481,-3.622) 64.129,-4.27 U6.16@67.252,-4.27 70.282,-4.27 C6.1@70.378,-4.366 ; C6.1@70.482,-4.262 70.482,-2.414 71.446,-1.45 74.575,-1.45 75.62,-2.495 75.62,-18.344 75.596,-18.368 75.596,-18.66 v1(75.491,-18.765) ; C28.2@111.283,-27.215 C29.2@113.765,-27.215 ; v2(113.765,-27.316) C29.2@113.765,-27.215 ; v1(113.94,-19.249) 114.924,-20.232 114.924,-26.057 C29.2@113.765,-27.215
  Bottom Layer w0.25: v1(75.491,-18.765) 79.278,-22.552 94.376,-22.552 97.221,-19.706 113.482,-19.706 v1(113.94,-19.249) ; v2(113.765,-27.316) 114.493,-28.045 116.269,-28.045 116.826,-27.488 U12.2@116.826,-27.17 116.826,-26.512 117.605,-25.732 121.097,-25.732 122.085,-26.72 W19.2@122.085,-27.275
3V3: JP1.4 Q2.1 Q3.1 Q4.1 R70.2 R72.2 R74.2 W16.2 | length 71
  Top Layer w0.25: v1(72.845,-6.13) 72.845,-6.279 73.138,-6.573 73.138,-6.953 73.596,-7.411 v1(73.596,-7.56) 73.596,-8.357 74.712,-9.472 v1(74.712,-12.947) ; R74.2@76.632,-8.847 76.632,-7.947 78.012,-6.567 Q4.1@78.012,-6.467
  Bottom Layer w0.25: Q2.1@62.844,-6.449 65.313,-6.449 R70.2@65.313,-6.499 ; R70.2@65.402,-6.539 70.381,-6.539 71.402,-7.56 v1(73.596,-7.56) v1@77.054,-7.56 ; JP1.4@72.729,-4.871 72.729,-6.015 v1(72.845,-6.13) ; v1(74.712,-12.947) 106.743,-12.947 W16.2@109.399,-15.603 ; v1(77.023,-7.544) 81.953,-7.544 82.431,-8.022 82.481,-8.022 82.856,-8.397 R72.2@82.856,-8.447 82.972,-8.563 Q3.1@85.374,-8.563
5V: C2.2 IC1.2 JP8.2 R1.2 R2.1 R4.2 R5.2 R6.1 R11.2 R71.2 R73.2 R75.2 U1.4 U1.6 U1.18 U2.8 U4.8 W12.2 | length 217.4
  Top Layer w0.2: R6.1@111.825,-4.654 111.853,-4.683 R2.1@111.853,-8.177
  Top Layer w0.25: R75.2@79.76,-2.028 82.637,-2.028 83.166,-1.499 JP8.2@87.28,-1.499 87.28,-1.793 88.664,-3.178 v1(88.664,-9.385) 87.279,-10.77 v1(87.279,-11.146) ; U1.18@80.541,-11.171 v1@82.062,-11.171 ; v1(82.102,-11.21) 82.102,-15.93 78.68,-19.352 78.68,-20.706 78.996,-21.022 U2.8@80.226,-21.022 81.763,-21.022 v1(82.139,-21.397) ; U1.6@89.126,-11.971 88.232,-11.971 87.407,-11.146 v1(87.279,-11.146) ; v1(97,-11.767) 97,-13.496 C2.2@95.312,-15.184 93.699,-13.571 U1.4@89.126,-13.571 88.292,-13.571 87.279,-12.558 v1(87.279,-11.146) ; v1(104.281,-11.661) 104.281,-14.98 R4.2@104.952,-15.652 105.003,-15.703 R5.2@105.003,-18.906 ; v1(106.573,-11.664) 107.297,-10.94 IC1.2@108.946,-10.94 110.4,-10.94 110.649,-10.691 110.649,-9.581 111.853,-8.377 R2.1@111.853,-8.177 ; R11.2@130.054,-10.214 127.848,-10.214 127.615,-9.982 127.615,-6.268 129.586,-4.297 U4.8@130.911,-4.297 ; v1(179.698,-3.875) 179.753,-3.82 W12.2@181.238,-3.82
  Bottom Layer w0.25: R71.2@58.954,-9.534 59.519,-9.534 61.595,-7.458 67.416,-7.458 68.143,-8.185 73.855,-8.185 74.13,-7.91 75.212,-7.91 75.471,-8.169 81.209,-8.169 82.263,-9.222 83.449,-9.222 83.496,-9.176 84.569,-9.176 84.681,-9.288 86.068,-9.288 86.18,-9.176 88.455,-9.176 v1(88.664,-9.385) 89.465,-8.584 R73.2@90.733,-8.584 ; v1(82.102,-11.21) 87.215,-11.21 v1(87.279,-11.146) ; v1(82.139,-21.397) v2@87.077,-21.397 ; v1(97,-11.767) 104.175,-11.767 v1(104.281,-11.661) 125.881,-11.661 v1(127.588,-9.954) 127.588,-4.795 131.052,-1.332 158.329,-1.332 160.873,-3.875 v1(179.698,-3.875)
  other v2: 87.044,-21.407
5V_IN: C52.1 C53.1 pad.1@184.319,-22.44 R59.2 U16.14 U16.15 U16.16 W12.1 | length 24.5
  Top Layer w0.25: C52.1@179.178,-16.412 180.888,-18.122 R59.2@181.272,-18.122 ; W12.1@182.538,-3.82 182.796,-3.82 183.381,-4.405 183.381,-8.632 183.381,-16.013 R59.2@181.272,-18.122 ; pad.1@184.319,-22.44 183.512,-22.44 181.272,-20.2 R59.2@181.272,-18.122
5VS: C10.2 C11.2 C12.2 C13.2 C32.2 C33.2 JP3.3 JP6.1 JP9.1 pad.1@18.87,-17.804 R8.1 U5.3 U7.1 U7.6 U8.8 U10.7 U11.7 U13.3 W14.2 | length 223
  Top Layer w0.25: v1(46.558,-23.617) 47.591,-24.65 U8.8@47.591,-27.875 47.591,-27.921 48.751,-29.081 71.126,-29.081 71.273,-28.935 R8.1@71.273,-20.71 ; C13.2@47.099,-14.831 48.367,-14.831 v1(48.907,-15.371) 48.907,-15.357 49.869,-14.394 54.132,-14.394 54.778,-15.041 C11.2@54.778,-15.047 ; C12.2@52.13,-16.206 53.849,-16.206 C10.2@54.455,-16.812 ; v1(53.885,-18.606) 54.455,-18.036 C10.2@54.455,-16.812 ; C11.2@54.455,-15.371 C10.2@54.455,-16.812 ; C10.2@54.815,-17.172 C10.2@54.455,-16.812 ; R8.1@71.434,-20.71 71.484,-20.71 72.688,-19.506 76.695,-19.506 78.701,-17.501 v1(78.738,-17.501) ; C32.2@118.852,-19.814 v1(118.852,-18.348) ; C32.2@118.923,-19.885 118.964,-19.926 C33.2@118.964,-22.609 125.062,-22.609 126.945,-24.493 U13.3@126.945,-26.448 ; v1(124.975,-1.924) 130.245,-1.924 130.951,-1.218 154.454,-1.218 W14.2@154.481,-1.244
  Top Layer w0.5: pad.1@18.87,-18.312 19.736,-19.177 JP3.3@29.381,-19.177 v1(29.381,-15.43) 29.381,-11.684 JP6.1@29.254,-11.557
  Bottom Layer w0.25: v2(29.341,-20.879) 36.075,-20.879 38.814,-23.617 v1(46.558,-23.617) ; v1(29.381,-15.43) 29.458,-15.507 v1@48.77,-15.507 ; U11.7@44.456,-18.952 45.325,-18.952 v1@48.77,-15.507 ; v1(48.907,-15.371) v1@48.77,-15.507 ; v1(53.885,-18.606) 54.232,-18.952 U10.7@55.357,-18.952 ; v1(78.738,-17.501) 107.175,-17.501 107.702,-18.027 118.531,-18.027 v1(118.852,-18.348) 122.69,-18.348 U5.3@122.99,-18.649 ; U7.1@118.979,-5.893 U7.6@121.679,-5.893 122.788,-5.893 124.984,-3.697 124.975,-3.688 v1(124.975,-1.924)
5VS_IN: C62.1 C63.1 Q6.2 R66.2 U17.14 U17.15 U17.16 | length 15.4
  Top Layer w0.25: C62.1@154.718,-17.025 156.29,-15.452 156.29,-11.291 R66.2@155.022,-10.023 157.955,-7.091 157.955,-6.471 Q6.2@159.676,-4.75
-3V: C17.1 C18.1 C19.1 U6.8 U6.12 U9.11 W18.2 | length 89.4
  Top Layer w0.25: U9.11@48.118,-6.717 49.292,-6.717 v1@49.683,-7.108 ; v1(59.883,-14.958) 59.883,-13.606 60.33,-13.16 U6.8@61.252,-13.16 62.44,-13.16 66.25,-9.35 U6.12@67.252,-9.35 ; v2(102.802,-23.415) 104.784,-23.415 107.58,-20.619 W18.2@107.928,-20.619
  Bottom Layer w0.25: C18.1@45.515,-5.741 C17.1@47.906,-5.741 48.097,-5.741 v1(49.589,-7.233) 49.414,-7.233 49.041,-7.606 49.041,-9.464 50.803,-11.225 64.235,-11.225 64.493,-10.967 64.448,-10.967 v1(64.493,-11.012) ; v1(59.883,-14.958) 60.616,-14.958 63.222,-17.564 63.222,-18.887 66.22,-21.885 68.247,-21.885 69.905,-23.542 v2@102.802,-23.542
-5V: C22.1 C23.1 C24.1 C25.1 pad.1@116.69,-4.809 R28.1 U10.4 U11.4 W17.1 | length 98.4
  Top Layer w0.25: R28.1@52.182,-18.409 52.182,-18.503 R28.1@52.29,-18.61 ; v1@52.29,-21.617 R28.1@52.29,-18.61 ; C22.1@56.442,-20.057 C23.1@54.446,-20.057 53.737,-20.057 R28.1@52.29,-18.61 ; v1(59.22,-21.492) 59.22,-13.102 v1(59.232,-13.09) ; v1(118.63,-10.431) 119.646,-9.415 119.646,-8.426 119.621,-8.426 119.621,-7.683 W17.1@119.646,-7.658
  Top Layer w0.5: pad.1@116.69,-4.809 117.333,-5.451 117.333,-9.134 v1(118.63,-10.431)
  Bottom Layer w0.25: U11.4@50.675,-21.492 52.132,-21.492 v1(52.273,-21.633) 53.007,-22.367 58.345,-22.367 v1(59.22,-21.492) U10.4@61.577,-21.492 ; v1(59.232,-13.09) 59.367,-12.955 68.033,-12.955 69.062,-11.926 91.4,-11.926 92.895,-10.431 v1(118.63,-10.431) ; pad.1@116.69,-4.809 pad.1@116.824,-4.943
-IN: C21.2 R33.2 R68.2 R69.1 U11.2 | length 32.1
  Top Layer w0.25: v1(53.007,-20.902) 53.007,-23.093 v1(53.095,-23.181) 53.095,-25.92 C21.2@53.295,-26.12 ; R69.1@63.591,-21.757 63.591,-25.62 R68.2@63.582,-25.629 65.092,-25.629 R33.2@67.528,-23.193 R33.2@67.378,-23.193
  Bottom Layer w0.25: U11.2@50.675,-18.952 51.074,-18.952 53.007,-20.885 v1(53.007,-20.902) ; v1@52.85,-23.193 R33.2@67.528,-23.193
A: JP5.1 R10.2 U4.6 | length 68.4
  Top Layer w0.25: U4.6@130.911,-6.837 R10.2@133.996,-6.837 ; R10.2@134.021,-6.812 134.226,-6.812 137.161,-3.877 v1(142.323,-3.877)
  Bottom Layer w0.25: v1@142.323,-3.931 154.77,-3.931 156.757,-5.918 183.889,-5.918 184.436,-6.466 184.436,-17.244 185.226,-18.034 JP5.1@185.928,-18.034
AIN0: JP6.3 U2.4 | length 67.2
  Top Layer w0.25: v1(38.176,-28.478) 38.209,-28.445 v1(38.209,-9.79) ; v1(72.853,-27.908) 72.853,-22.918 74.249,-21.522 U2.4@75.826,-21.522
  Bottom Layer w0.25: v2@33.199,-9.79 v1(38.209,-9.79) ; v1(38.176,-28.478) 52.573,-28.478 52.596,-28.456 72.305,-28.456 v1(72.853,-27.908)
  other v2: 33.199,-9.783
AIN1: C15.1 R17.1 U2.5 | length 33.4
  Top Layer w0.25: R17.1@50.877,-23.363 v1(50.877,-24.699) 50.877,-26.036 C15.1@50.892,-26.05 ; v1(73.869,-26.553) 73.869,-22.85 74.697,-22.022 U2.5@75.826,-22.022
  Bottom Layer w0.25: v1(50.877,-24.699) 53.886,-27.708 72.169,-27.708 73.325,-26.553 v1(73.869,-26.553)
AIN2: R16.2 U2.6 U10.6 | length 38.6
  Top Layer w0.25: v1(55.74,-24.993) 55.815,-24.993 57.77,-23.038 v1(57.77,-20.242) ; v1(74.854,-24.511) 76.339,-24.511 78.828,-22.022 U2.6@80.226,-22.022
  Bottom Layer w0.25: U10.6@55.357,-20.222 57.75,-20.222 v1(57.77,-20.242) ; R16.2@55.741,-26.524 v1(55.74,-24.993) v1(55.74,-24.993) 56.515,-24.219 57.917,-24.219 58.41,-24.712 58.41,-26.305 58.979,-26.874 72.178,-26.874 74.682,-24.37 74.822,-24.511 v1(74.854,-24.511)
AIN3: C27.1 D3.2 R32.1 U2.7 | length 48.2
  Top Layer w0.25: R32.1@40.301,-10.811 v1@41.193,-10.811 ; v1(65.275,-11.816) 65.289,-11.829 65.289,-12.77 67.807,-15.288 v1(67.807,-18.375) ; v3(78.177,-18.971) 78.177,-21.078 78.621,-21.522 U2.7@80.226,-21.522
  Bottom Layer w0.25: v1@41.395,-10.846 C27.1@43.098,-10.846 46.175,-10.846 47.145,-11.816 v1(65.275,-11.816) ; v1(67.807,-18.375) 67.938,-18.506 74.398,-18.506 74.991,-17.913 75.862,-17.913 76.92,-18.971 v3(78.177,-18.971)
  other v1: 41.312,-10.929
B: JP5.2 U4.7 W15.2 | length 73.8
  Top Layer w0.25: U4.7@130.911,-5.567 133.852,-5.567 135.887,-3.533 v1(135.828,-3.533) ; W15.2@139.274,-6.812 139.94,-6.812 140.716,-6.035 v1(140.716,-4.699)
  Bottom Layer w0.25: v1(135.828,-3.533) 139.55,-3.533 v1@140.666,-4.649 ; JP5.2@185.928,-16.034 186.701,-16.034 188.092,-14.644 188.092,-8.19 184.758,-4.856 158.644,-4.856 157.04,-3.252 142.064,-3.252 v1@140.666,-4.649 ; v1@140.666,-4.649 140.619,-4.697 140.621,-4.699 v1(140.716,-4.699) v1@140.666,-4.649
COND.+: JP7.1 pad.3@15.255,-12.319 R14.1 U9.1 | length 47.5
  Top Layer w0.25: U9.1@54.118,-10.467 56.469,-10.467 R14.1@56.608,-10.328 56.608,-11.545 v1(55.205,-12.948)
  Bottom Layer w0.25: pad.3@15.255,-12.319 15.255,-13.022 16.589,-14.356 20.164,-14.356 21.401,-13.119 55.034,-13.119 v1(55.205,-12.948)
COND.-: JP7.2 pad.2@17.795,-12.319 R29.2 R36.1 U9.9 | length 35.3
  Top Layer w0.25: v1(41.607,-4.299) 41.799,-4.491 41.799,-4.905 R36.1@42.891,-5.996 R29.2@45.547,-5.996 47.326,-4.217 U9.9@48.118,-4.217
  Bottom Layer w0.25: pad.2@17.795,-12.319 18.369,-12.319 26.244,-4.444 41.462,-4.444 v1(41.607,-4.299)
